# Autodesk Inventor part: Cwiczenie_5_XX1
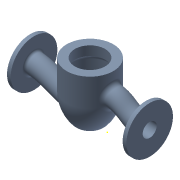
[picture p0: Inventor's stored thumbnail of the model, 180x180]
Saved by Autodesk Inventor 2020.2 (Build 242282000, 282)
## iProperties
Created: 2010-12
Part Number: Cwiczenie_5_XX1
Document SubType Name: Modeling
Designer: F.Stasiak
Density: 1 g/cm^3
Material: Ogólny
Appearance: Stalowoniebieska - jasna
Manager: www.cadconsulting.pl
Company: Fabian Stasiak CAD Consulting
Author: F.Stasiak
Subject: Zbiór ćwiczeń. Autodesk Inventor 2020. Kurs podstawowy
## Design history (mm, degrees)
sketch "Szkic2"
  geometry: L1 (0, 0)-(0, 120); L2 (0, 120)-(50, 120); L3 (50, 120)-(50, 60); L4 (25, 0)-(0, 0); L5 (32.5, 120)-(32.5, 100); L6 (40, 50)-(0, 50); L7 (20, 50)-(20, 5); L8 (20, 5)-(0, 5); L9 (32.5, 100)-(40, 100); L10 (40, 100)-(40, 50); A1 r 84.5 centre (-34.5, 60) between (25, 0) and (50, 60)
  constraints: 20 end point, 7 perpendicular, 3 point on line, 2 parallel, 2 point on circle, 1 centre point, 1 midpoint, 1 tangent, 1 vertical
  dimensions: "d3" = 120 distance of L1.start L1.end; "d5" = 60 distance of L2.end L3.end; "d7" = 20 distance of L5.start L5.end; "d8" = 100 diameter of L3 L1; "d9" = 65 diameter of L5 L1; "d10" = 80 diameter of L10 L1; "d11" = 70 distance between parallel lines of L6 L2; "d12" = 40 diameter of L7 L1; "d13" = 50 diameter of L4.start L1; "d14" = 5 distance between parallel lines of L8 L4
revolve "Obrót1" sketch "Szkic2" stored, may be unused: angle "d15" = 90 deg
fillet "Zaokrąglenie1" dims "d20" = 10
fillet "Zaokrąglenie2" dims "d21" = 10
fillet "Zaokrąglenie3" dims "d22" = 15
node "Płaszczyzna konstrukcyjna1"
node "Płaszczyzna konstrukcyjna2"
sketch "Szkic3"
  geometry: C1 r 50 at (0, 50); 1 further point
  constraints: 1 centre point
  dimensions: "d25" = 100 diameter of C1; "d26" = 50 distance of point (0, 0) C1.centre
extrude "Wyciągnięcie proste2" join sketch "Szkic3" distance "d28" = 8; taper "d29" = 0 deg
node "Płaszczyzna konstrukcyjna3"
sketch "Szkic4"
  geometry: C1 r 20 at (0, 75); 1 further point
  constraints: 1 centre point, 1 vertical alignment
  dimensions: "d31" = 40 diameter of C1; "d32" = 75 distance of point (0, 0) C1.centre
sketch "Szkic5"
  geometry: C1 r 20 at (0, 0); 2 further points
  constraints: 2 horizontal alignment, 1 centre point, 1 other
  dimensions: "d33" = 40 diameter of C1
feature "Wyciągnięcie złożone1" sketch "Szkic4", "Szkic5" dims "d34" = 110, "d35" = 90 deg, "d36" = 110, "d37" = 90 deg
node "Płaszczyzna konstrukcyjna4"
sketch "Szkic7"
  geometry: 1 further point
sketch "Szkic8"
  geometry: C1 r 15 at (0, 75); 2 further points
  constraints: 1 centre point, 1 coincident
  dimensions: "d41" = 30 diameter of C1
sketch "Szkic9"
  geometry: C1 r 15 at (0, 0); 2 further points
  constraints: 1 centre point, 1 coincident, 1 horizontal alignment
  dimensions: "d42" = 30 diameter of C1
feature "Wyciągnięcie złożone2" sketch "Szkic9" dims "d43" = 160, "d44" = 90 deg, "d45" = 160, "d46" = 90 deg
sketch "Szkic10"
  geometry: 2 further points
  constraints: 1 vertical alignment
extrude "Wyciągnięcie proste3" join sketch "Szkic10" distance "d47" = 8; taper "d48" = 0 deg
node "Płaszczyzna konstrukcyjna6"
sketch "Szkic11"
  geometry: C1 r 20 at (0, 25); 1 further point
  constraints: 1 centre point, 1 vertical alignment
  dimensions: "d50" = 40 diameter of C1; "d51" = 25 distance of point (0, 0) C1.centre
sketch "Szkic12"
  geometry: C1 r 20 at (0, 0); 2 further points
  constraints: 1 centre point, 1 coincident, 1 horizontal alignment
  dimensions: "d52" = 40 diameter of C1
feature "Wyciągnięcie złożone3" sketch "Szkic11", "Szkic12" dims "d53" = 100, "d54" = 90 deg, "d55" = 100, "d56" = 90 deg
node "Płaszczyzna konstrukcyjna7"
sketch "Szkic13"
  geometry: C1 r 15 at (0, 25); 2 further points
  constraints: 1 centre point, 1 coincident
  dimensions: "d58" = 30 diameter of C1
sketch "Szkic14"
  geometry: C1 r 15 at (0, 0); 2 further points
  constraints: 1 centre point, 1 coincident, 1 horizontal alignment
  dimensions: "d59" = 30 diameter of C1
feature "Wyciągnięcie złożone4" sketch "Szkic13", "Szkic14" dims "d60" = 140, "d61" = 90 deg, "d62" = 140, "d63" = 90 deg
fillet "Zaokrąglenie4" dims "d64" = 5
fillet "Zaokrąglenie5" dims "d65" = 10
node "Bryła2"
other parameters: "d30" = 45, "d40" = -8, "d57" = 8
